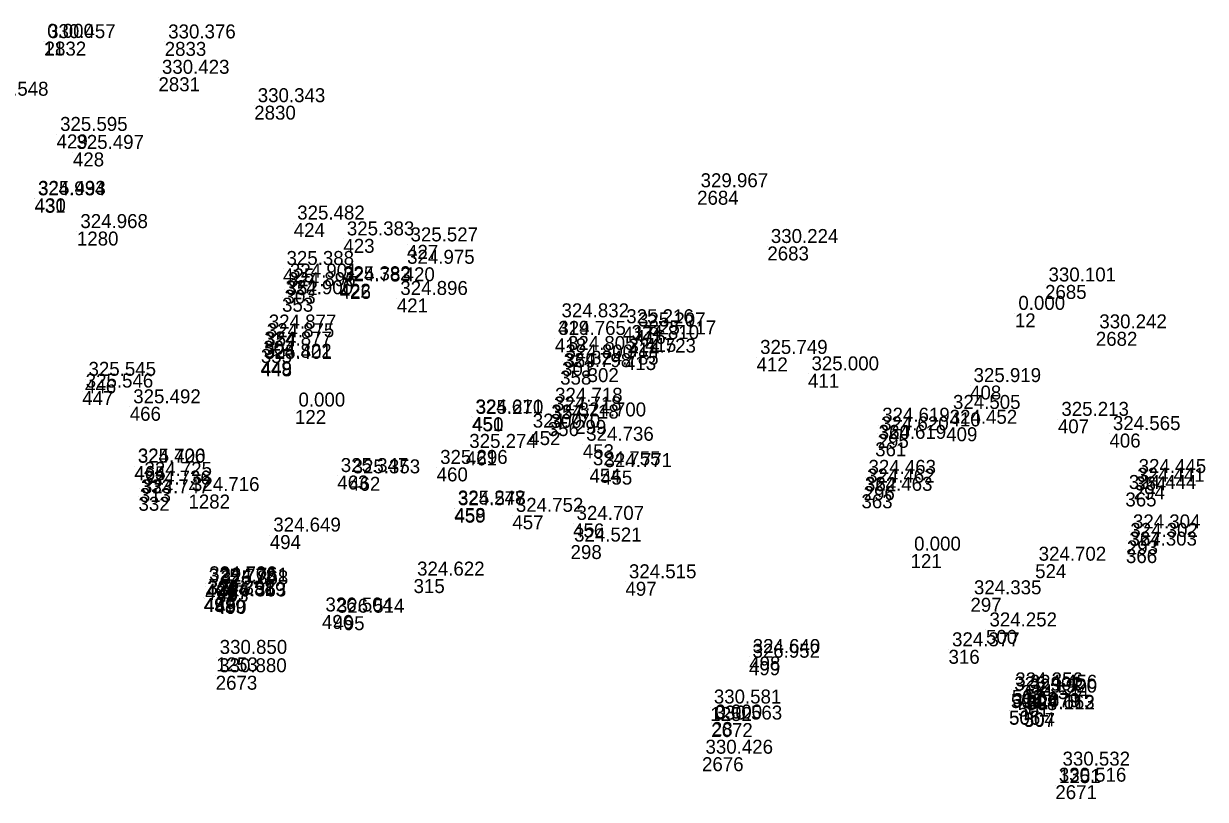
# Model space of a CAD drawing. Extents: x -829398 to -819400, y -1074439 to -1067977.
# Drawn here: x -823162.7 to -823061.1, y -1070442.9 to -1070376.3 of the extents above; entities that cross this region are included whole.
import ezdxf

# ---------------------------------------------------------------- set-up
doc = ezdxf.new("R2010")
doc.units = 0
doc.layers.add('Vrstva 60', color=7, linetype='Continuous')
doc.layers.add('Vrstva 61', color=7, linetype='Continuous')

msp = doc.modelspace()

# ---------------------------------------------------------------- linework, layer by layer
at = {"layer": 'Vrstva 60'}
for p, q in [((-823160.939, -1070377.802), (-823160.939, -1070377.802)), ((-823160.86, -1070377.829), (-823160.86, -1070377.829)), ((-823150.54, -1070377.853), (-823150.54, -1070377.853)), ((-823151.077, -1070380.891), (-823151.077, -1070380.891)), ((-823142.846, -1070383.328), (-823142.846, -1070383.328)), ((-823159.831, -1070385.796), (-823159.831, -1070385.796)), ((-823158.426, -1070387.344), (-823158.426, -1070387.344)), ((-823104.789, -1070390.636), (-823104.789, -1070390.636)), ((-823161.738, -1070391.33), (-823161.738, -1070391.33)), ((-823161.712, -1070391.288), (-823161.712, -1070391.288)), ((-823139.454, -1070393.406), (-823139.454, -1070393.406)), ((-823158.086, -1070394.141), (-823158.086, -1070394.141)), ((-823135.189, -1070394.769), (-823135.189, -1070394.769)), ((-823129.717, -1070395.284), (-823129.717, -1070395.284)), ((-823098.755, -1070395.423), (-823098.755, -1070395.423)), ((-823140.372, -1070397.31), (-823140.372, -1070397.31)), ((-823130.01, -1070397.21), (-823130.01, -1070397.21)), ((-823140.077, -1070398.392), (-823140.077, -1070398.392)), ((-823135.513, -1070398.622), (-823135.513, -1070398.622)), ((-823135.496, -1070398.728), (-823135.496, -1070398.728)), ((-823074.893, -1070398.728), (-823074.893, -1070398.728)), ((-823140.456, -1070399.824), (-823140.456, -1070399.824)), ((-823140.247, -1070399.133), (-823140.247, -1070399.133)), ((-823130.595, -1070399.886), (-823130.595, -1070399.886)), ((-823116.743, -1070401.807), (-823116.743, -1070401.807)), ((-823077.485, -1070401.167), (-823077.485, -1070401.167)), ((-823141.898, -1070402.769), (-823141.898, -1070402.769)), ((-823111.178, -1070402.313), (-823111.178, -1070402.313)), ((-823110.169, -1070402.592), (-823110.169, -1070402.592)), ((-823070.529, -1070402.753), (-823070.529, -1070402.753)), ((-823142.069, -1070403.512), (-823142.069, -1070403.512)), ((-823117.013, -1070403.317), (-823117.013, -1070403.317)), ((-823110.724, -1070403.679), (-823110.724, -1070403.679)), ((-823109.256, -1070403.278), (-823109.256, -1070403.278)), ((-823142.275, -1070404.227), (-823142.275, -1070404.227)), ((-823116.187, -1070404.612), (-823116.187, -1070404.612)), ((-823110.993, -1070404.833), (-823110.993, -1070404.833)), ((-823099.678, -1070404.949), (-823099.678, -1070404.949)), ((-823142.298, -1070405.281), (-823142.298, -1070405.281)), ((-823142.28, -1070405.373), (-823142.28, -1070405.373)), ((-823116.394, -1070405.332), (-823116.394, -1070405.332)), ((-823114.2, -1070405.871), (-823114.2, -1070405.871)), ((-823157.388, -1070406.832), (-823157.388, -1070406.832)), ((-823116.558, -1070406.085), (-823116.558, -1070406.085)), ((-823095.262, -1070406.36), (-823095.262, -1070406.36)), ((-823157.629, -1070407.839), (-823157.629, -1070407.839)), ((-823081.335, -1070407.369), (-823081.335, -1070407.369)), ((-823117.293, -1070409.059), (-823117.293, -1070409.059)), ((-823153.545, -1070409.192), (-823153.545, -1070409.192)), ((-823139.347, -1070409.469), (-823139.347, -1070409.469)), ((-823124.136, -1070410.062), (-823124.136, -1070410.062)), ((-823124.105, -1070410.098), (-823124.105, -1070410.098)), ((-823117.385, -1070409.809), (-823117.385, -1070409.809)), ((-823083.103, -1070409.675), (-823083.103, -1070409.675)), ((-823117.623, -1070410.503), (-823117.623, -1070410.503)), ((-823115.276, -1070410.317), (-823115.276, -1070410.317)), ((-823089.185, -1070410.769), (-823089.185, -1070410.769)), ((-823083.388, -1070410.95), (-823083.388, -1070410.95)), ((-823073.79, -1070410.268), (-823073.79, -1070410.268)), ((-823119.214, -1070411.28), (-823119.214, -1070411.28)), ((-823089.279, -1070411.517), (-823089.279, -1070411.517)), ((-823069.359, -1070411.489), (-823069.359, -1070411.489)), ((-823124.669, -1070413.021), (-823124.669, -1070413.021)), ((-823114.618, -1070412.408), (-823114.618, -1070412.408)), ((-823089.489, -1070412.243), (-823089.489, -1070412.243)), ((-823153.15, -1070414.301), (-823153.15, -1070414.301)), ((-823153.148, -1070414.276), (-823153.148, -1070414.276)), ((-823135.712, -1070415.094), (-823135.712, -1070415.094)), ((-823127.172, -1070414.397), (-823127.172, -1070414.397)), ((-823114.041, -1070414.512), (-823114.041, -1070414.512)), ((-823113.045, -1070414.671), (-823113.045, -1070414.671)), ((-823067.15, -1070415.177), (-823067.15, -1070415.177)), ((-823152.682, -1070416.169), (-823152.682, -1070416.169)), ((-823152.579, -1070415.426), (-823152.579, -1070415.426)), ((-823134.694, -1070415.206), (-823134.694, -1070415.206)), ((-823090.486, -1070416.001), (-823090.486, -1070416.001)), ((-823090.363, -1070415.251), (-823090.363, -1070415.251)), ((-823067.272, -1070415.932), (-823067.272, -1070415.932)), ((-823152.795, -1070416.922), (-823152.795, -1070416.922)), ((-823148.498, -1070416.726), (-823148.498, -1070416.726)), ((-823090.67, -1070416.708), (-823090.67, -1070416.708)), ((-823067.991, -1070416.55), (-823067.991, -1070416.55)), ((-823125.649, -1070417.884), (-823125.649, -1070417.884)), ((-823125.637, -1070417.943), (-823125.637, -1070417.943)), ((-823120.667, -1070418.512), (-823120.667, -1070418.512)), ((-823115.45, -1070419.205), (-823115.45, -1070419.205)), ((-823141.509, -1070420.208), (-823141.509, -1070420.208)), ((-823067.638, -1070419.937), (-823067.638, -1070419.937)), ((-823115.664, -1070421.065), (-823115.664, -1070421.065)), ((-823067.864, -1070420.666), (-823067.864, -1070420.666)), ((-823086.445, -1070421.842), (-823086.445, -1070421.842)), ((-823067.94, -1070421.413), (-823067.94, -1070421.413)), ((-823075.741, -1070422.708), (-823075.741, -1070422.708)), ((-823129.155, -1070423.987), (-823129.155, -1070423.987)), ((-823110.949, -1070424.22), (-823110.949, -1070424.22)), ((-823147.068, -1070424.591), (-823147.068, -1070424.591)), ((-823147.016, -1070424.393), (-823147.016, -1070424.393)), ((-823146.045, -1070424.511), (-823146.045, -1070424.511)), ((-823146.022, -1070424.738), (-823146.022, -1070424.738)), ((-823147.19, -1070425.611), (-823147.19, -1070425.611)), ((-823147.138, -1070425.616), (-823147.138, -1070425.616)), ((-823146.266, -1070425.734), (-823146.266, -1070425.734)), ((-823146.192, -1070425.775), (-823146.192, -1070425.775)), ((-823081.303, -1070425.595), (-823081.303, -1070425.595)), ((-823137.029, -1070427.07), (-823137.029, -1070427.07)), ((-823136.045, -1070427.174), (-823136.045, -1070427.174)), ((-823079.968, -1070428.355), (-823079.968, -1070428.355)), ((-823083.185, -1070430.062), (-823083.185, -1070430.062)), ((-823146.116, -1070430.714), (-823146.116, -1070430.714)), ((-823100.333, -1070431.042), (-823100.333, -1070431.042)), ((-823100.315, -1070430.637), (-823100.315, -1070430.637)), ((-823146.159, -1070432.29), (-823146.159, -1070432.29)), ((-823077.834, -1070433.862), (-823077.834, -1070433.862)), ((-823077.748, -1070433.503), (-823077.748, -1070433.503)), ((-823076.528, -1070434.039), (-823076.528, -1070434.039)), ((-823076.515, -1070433.706), (-823076.515, -1070433.706)), ((-823103.654, -1070434.976), (-823103.654, -1070434.976)), ((-823077.99, -1070435.299), (-823077.99, -1070435.299)), ((-823077.98, -1070435.275), (-823077.98, -1070435.275)), ((-823077.231, -1070434.594), (-823077.231, -1070434.594)), ((-823076.735, -1070435.433), (-823076.735, -1070435.433)), ((-823076.71, -1070435.486), (-823076.71, -1070435.486)), ((-823103.584, -1070436.353), (-823103.584, -1070436.353)), ((-823103.522, -1070436.264), (-823103.522, -1070436.264)), ((-823104.369, -1070439.286), (-823104.369, -1070439.286)), ((-823073.689, -1070440.31), (-823073.689, -1070440.31)), ((-823074.008, -1070441.689), (-823074.008, -1070441.689))]:
    msp.add_line(p, q, dxfattribs=at)

# ---------------------------------------------------------------- texts
for s, p in [('11', (-823160.939, -1070379.002)), ('2832', (-823160.86, -1070379.029)), ('2833', (-823150.54, -1070379.053)), ('2831', (-823151.077, -1070382.091)), ('2830', (-823142.846, -1070384.528)), ('429', (-823159.831, -1070386.996)), ('428', (-823158.426, -1070388.544)), ('2684', (-823104.789, -1070391.836)), ('431', (-823161.738, -1070392.53)), ('430', (-823161.712, -1070392.488)), ('424', (-823139.454, -1070394.606)), ('1280', (-823158.086, -1070395.341)), ('423', (-823135.189, -1070395.969)), ('427', (-823129.717, -1070396.484)), ('2683', (-823098.755, -1070396.623)), ('425', (-823140.372, -1070398.51)), ('420', (-823130.01, -1070398.41)), ('352', (-823140.077, -1070399.592)), ('422', (-823135.513, -1070399.822)), ('426', (-823135.496, -1070399.928)), ('2685', (-823074.893, -1070399.928)), ('353', (-823140.456, -1070401.024)), ('303', (-823140.247, -1070400.333)), ('421', (-823130.595, -1070401.086)), ('419', (-823116.743, -1070403.007)), ('12', (-823077.485, -1070402.367)), ('354', (-823141.898, -1070403.969)), ('417', (-823111.178, -1070403.513)), ('416', (-823110.169, -1070403.792)), ('2682', (-823070.529, -1070403.953)), ('304', (-823142.069, -1070404.712)), ('418', (-823117.013, -1070404.517)), ('414', (-823110.724, -1070404.879)), ('415', (-823109.256, -1070404.478)), ('355', (-823142.275, -1070405.427)), ('359', (-823116.187, -1070405.812)), ('413', (-823110.993, -1070406.033)), ('412', (-823099.678, -1070406.149)), ('449', (-823142.298, -1070406.481)), ('448', (-823142.28, -1070406.573)), ('301', (-823116.394, -1070406.532)), ('302', (-823114.2, -1070407.071)), ('446', (-823157.388, -1070408.032)), ('358', (-823116.558, -1070407.285)), ('411', (-823095.262, -1070407.56)), ('447', (-823157.629, -1070409.039)), ('408', (-823081.335, -1070408.569)), ('357', (-823117.293, -1070410.259)), ('466', (-823153.545, -1070410.392)), ('122', (-823139.347, -1070410.669)), ('451', (-823124.136, -1070411.262)), ('450', (-823124.105, -1070411.298)), ('300', (-823117.385, -1070411.009)), ('410', (-823083.103, -1070410.875)), ('356', (-823117.623, -1070411.703)), ('299', (-823115.276, -1070411.517)), ('360', (-823089.185, -1070411.969)), ('409', (-823083.388, -1070412.15)), ('407', (-823073.79, -1070411.468)), ('452', (-823119.214, -1070412.48)), ('295', (-823089.279, -1070412.717)), ('406', (-823069.359, -1070412.689)), ('461', (-823124.669, -1070414.221)), ('453', (-823114.618, -1070413.608)), ('361', (-823089.489, -1070413.443)), ('465', (-823153.15, -1070415.501)), ('464', (-823153.148, -1070415.476)), ('463', (-823135.712, -1070416.294)), ('462', (-823134.694, -1070416.406)), ('460', (-823127.172, -1070415.597)), ('454', (-823114.041, -1070415.712)), ('455', (-823113.045, -1070415.871)), ('364', (-823067.15, -1070416.377)), ('313', (-823152.682, -1070417.369)), ('333', (-823152.579, -1070416.626)), ('296', (-823090.486, -1070417.201)), ('362', (-823090.363, -1070416.451)), ('294', (-823067.272, -1070417.132)), ('332', (-823152.795, -1070418.122)), ('1282', (-823148.498, -1070417.926)), ('363', (-823090.67, -1070417.908)), ('365', (-823067.991, -1070417.75)), ('458', (-823125.649, -1070419.084)), ('459', (-823125.637, -1070419.143)), ('457', (-823120.667, -1070419.712)), ('456', (-823115.45, -1070420.405)), ('494', (-823141.509, -1070421.408)), ('367', (-823067.638, -1070421.137)), ('298', (-823115.664, -1070422.265)), ('293', (-823067.864, -1070421.866)), ('121', (-823086.445, -1070423.042)), ('366', (-823067.94, -1070422.613)), ('524', (-823075.741, -1070423.908)), ('315', (-823129.155, -1070425.187)), ('497', (-823110.949, -1070425.42)), ('492', (-823147.068, -1070425.791)), ('486', (-823147.016, -1070425.593)), ('487', (-823146.045, -1070425.711)), ('493', (-823146.022, -1070425.938)), ('491', (-823147.19, -1070426.811)), ('488', (-823147.138, -1070426.816)), ('489', (-823146.266, -1070426.934)), ('490', (-823146.192, -1070426.975)), ('297', (-823081.303, -1070426.795)), ('496', (-823137.029, -1070428.27)), ('495', (-823136.045, -1070428.374)), ('500', (-823079.968, -1070429.555)), ('316', (-823083.185, -1070431.262)), ('1253', (-823146.116, -1070431.914)), ('499', (-823100.333, -1070432.242)), ('498', (-823100.315, -1070431.837)), ('2673', (-823146.159, -1070433.49)), ('509', (-823077.834, -1070435.062)), ('502', (-823077.748, -1070434.703)), ('508', (-823076.528, -1070435.239)), ('503', (-823076.515, -1070434.906)), ('1252', (-823103.654, -1070436.176)), ('506', (-823077.99, -1070436.499)), ('505', (-823077.98, -1070436.475)), ('501', (-823077.231, -1070435.794)), ('504', (-823076.735, -1070436.633)), ('507', (-823076.71, -1070436.686)), ('2672', (-823103.584, -1070437.553)), ('28', (-823103.522, -1070437.464)), ('2676', (-823104.369, -1070440.486)), ('1251', (-823073.689, -1070441.51)), ('2671', (-823074.008, -1070442.889))]:
    msp.add_text(s, height=1.2, dxfattribs=at).set_placement(p)
at = {"layer": 'Vrstva 61'}
for s, p in [('0.000', (-823160.639, -1070377.502)), ('330.457', (-823160.56, -1070377.529)), ('330.376', (-823150.24, -1070377.553)), ('330.423', (-823150.777, -1070380.591)), ('325.548', (-823166.33, -1070382.475)), ('330.343', (-823142.546, -1070383.028)), ('325.595', (-823159.531, -1070385.496)), ('325.497', (-823158.126, -1070387.044)), ('325.493', (-823161.412, -1070390.988)), ('329.967', (-823104.489, -1070390.336)), ('324.934', (-823161.438, -1070391.03)), ('324.968', (-823157.786, -1070393.841)), ('325.482', (-823139.154, -1070393.106)), ('325.383', (-823134.889, -1070394.469)), ('325.527', (-823129.417, -1070394.984)), ('330.224', (-823098.455, -1070395.123)), ('325.388', (-823140.072, -1070397.01)), ('324.975', (-823129.71, -1070396.91)), ('324.901', (-823139.777, -1070398.092)), ('324.896', (-823139.947, -1070398.833)), ('325.382', (-823135.213, -1070398.322)), ('324.783', (-823135.196, -1070398.428)), ('330.101', (-823074.593, -1070398.428)), ('324.900', (-823140.156, -1070399.524)), ('324.896', (-823130.295, -1070399.586)), ('0.000', (-823077.185, -1070400.867)), ('324.832', (-823116.443, -1070401.507)), ('325.216', (-823110.878, -1070402.013)), ('324.877', (-823141.598, -1070402.469)), ('324.765', (-823116.713, -1070403.017)), ('325.207', (-823109.869, -1070402.292)), ('325.117', (-823108.956, -1070402.978)), ('330.242', (-823070.229, -1070402.453)), ('324.877', (-823141.975, -1070403.927)), ('324.875', (-823141.769, -1070403.212)), ('324.810', (-823110.424, -1070403.379)), ('324.822', (-823141.998, -1070404.981)), ('325.401', (-823141.98, -1070405.073)), ('324.800', (-823116.094, -1070405.032)), ('324.805', (-823115.887, -1070404.312)), ('324.723', (-823110.693, -1070404.533)), ('325.749', (-823099.378, -1070404.649)), ('324.798', (-823116.258, -1070405.785)), ('324.785', (-823113.9, -1070405.571)), ('325.000', (-823094.962, -1070406.06)), ('325.545', (-823157.088, -1070406.532)), ('325.919', (-823081.035, -1070407.069)), ('325.546', (-823157.329, -1070407.539)), ('325.492', (-823153.245, -1070408.892)), ('0.000', (-823139.047, -1070409.169)), ('324.718', (-823116.993, -1070408.759)), ('324.611', (-823123.836, -1070409.762)), ('325.270', (-823123.805, -1070409.798)), ('324.718', (-823117.323, -1070410.203)), ('324.718', (-823117.085, -1070409.509)), ('324.700', (-823114.976, -1070410.017)), ('324.505', (-823082.803, -1070409.375)), ('325.213', (-823073.49, -1070409.968)), ('324.770', (-823118.914, -1070410.98)), ('324.620', (-823088.979, -1070411.217)), ('324.619', (-823088.885, -1070410.469)), ('324.452', (-823083.088, -1070410.65)), ('324.565', (-823069.059, -1070411.189)), ('324.736', (-823114.318, -1070412.108)), ('324.619', (-823089.189, -1070411.943)), ('325.274', (-823124.369, -1070412.721)), ('324.720', (-823152.85, -1070414.001)), ('325.406', (-823152.848, -1070413.976)), ('325.296', (-823126.872, -1070414.097)), ('324.755', (-823113.741, -1070414.212)), ('324.771', (-823112.745, -1070414.371)), ('324.725', (-823152.279, -1070415.126)), ('325.347', (-823135.412, -1070414.794)), ('325.353', (-823134.394, -1070414.906)), ('324.463', (-823090.063, -1070414.951)), ('324.445', (-823066.85, -1070414.877)), ('324.736', (-823152.382, -1070415.869)), ('324.462', (-823090.186, -1070415.701)), ('324.444', (-823067.691, -1070416.25)), ('324.441', (-823066.972, -1070415.632)), ('324.747', (-823152.495, -1070416.622)), ('324.716', (-823148.198, -1070416.426)), ('324.463', (-823090.37, -1070416.408)), ('325.248', (-823125.349, -1070417.584)), ('324.577', (-823125.337, -1070417.643)), ('324.752', (-823120.367, -1070418.212)), ('324.707', (-823115.15, -1070418.905)), ('324.649', (-823141.209, -1070419.908)), ('324.302', (-823067.564, -1070420.366)), ('324.304', (-823067.338, -1070419.637)), ('324.521', (-823115.364, -1070420.765)), ('324.303', (-823067.64, -1070421.113)), ('0.000', (-823086.145, -1070421.542)), ('324.702', (-823075.441, -1070422.408)), ('325.778', (-823146.768, -1070424.291)), ('324.706', (-823146.716, -1070424.093)), ('324.751', (-823145.745, -1070424.211)), ('325.868', (-823145.722, -1070424.438)), ('324.622', (-823128.855, -1070423.687)), ('324.515', (-823110.649, -1070423.92)), ('326.358', (-823146.89, -1070425.311)), ('324.792', (-823146.838, -1070425.316)), ('324.819', (-823145.966, -1070425.434)), ('326.363', (-823145.892, -1070425.475)), ('324.335', (-823081.003, -1070425.295)), ('326.504', (-823136.729, -1070426.77)), ('326.514', (-823135.745, -1070426.874)), ('324.252', (-823079.668, -1070428.055)), ('330.850', (-823145.816, -1070430.414)), ('324.640', (-823100.015, -1070430.337)), ('324.377', (-823082.885, -1070429.762)), ('326.952', (-823100.033, -1070430.742)), ('330.880', (-823145.859, -1070431.99)), ('325.901', (-823077.534, -1070433.562)), ('324.356', (-823077.448, -1070433.203)), ('324.456', (-823076.215, -1070433.406)), ('330.581', (-823103.354, -1070434.676)), ('324.544', (-823076.931, -1070434.294)), ('325.920', (-823076.228, -1070433.739)), ('327.079', (-823077.69, -1070434.999)), ('324.679', (-823077.68, -1070434.975)), ('324.663', (-823076.435, -1070435.133)), ('327.112', (-823076.41, -1070435.186)), ('330.563', (-823103.284, -1070436.053)), ('0.000', (-823103.222, -1070435.964)), ('330.426', (-823104.069, -1070438.986)), ('330.532', (-823073.389, -1070440.01)), ('330.516', (-823073.708, -1070441.389))]:
    msp.add_text(s, height=1.2, dxfattribs=at).set_placement(p)

doc.saveas('drawing.dxf')
